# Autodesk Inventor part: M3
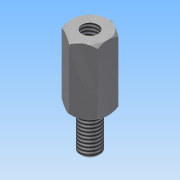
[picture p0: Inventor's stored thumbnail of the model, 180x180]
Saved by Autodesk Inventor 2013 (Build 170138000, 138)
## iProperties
Created: 2012-08
Part Number: M3
Material: Steel
Document SubType Name: Modeling
Designer: rYan
Density: 7.85 g/cm^3
Mass: 2.13082 g
Surface Area: 3.45472 cm^2
Volume: 0.271442 cm^3
Author: rYan
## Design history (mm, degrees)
derived "Abstandsbolzen Typ B.ipt"
feature "Volumenkörper1::Abstandsbolzen Typ B.ipt"
tag "TaggingFeature1"
body "Solid1"
other parameters: "SW" = 5.5, "d2" = 0, "l_" = 6.5, "d9" = 118 deg, "GA_" = 3, "A_" = 6, "d13" = 0, "d17" = 0.25, "d20" = 45 deg
